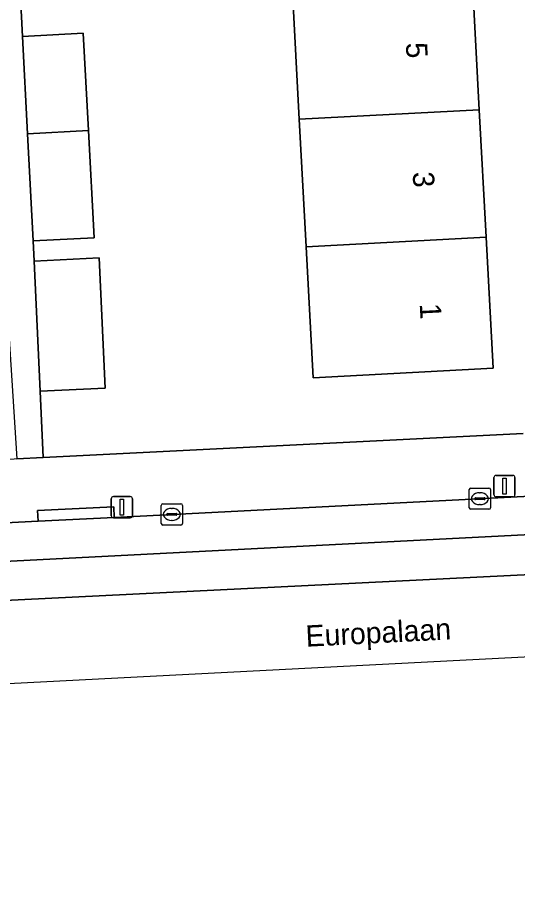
# Model space of a CAD drawing. Extents: x 160554 to 161248, y 385329 to 386506.
# Drawn here: x 161046.43 to 161069.93, y 385329.84 to 385370.85 of the extents above; entities that cross this region are included whole.
import ezdxf

# ---------------------------------------------------------------- set-up
doc = ezdxf.new("R2010")
doc.units = 0
for name, color, linetype in [('IMGEO_Erf', 7, 'Continuous'), ('IMGEO_Fietspad_gesloten', 7, 'Continuous'), ('IMGEO_Kolk', 7, 'Continuous'), ('IMGEO_Lichtmast', 7, 'Continuous'), ('IMGEO_Openbare_ruimte_label', 7, 'Continuous'), ('IMGEO_Pand', 7, 'Continuous'), ('IMGEO_Pand_nummerreeks', 7, 'Continuous'), ('IMGEO_Parkeervlak_open', 7, 'Continuous'), ('IMGEO_Rijbaan_lokaal_gesloten', 7, 'Continuous'), ('IMGEO_Voetpad_open', 7, 'Continuous')]:
    doc.layers.add(name, color=color, linetype=linetype)

msp = doc.modelspace()

# ---------------------------------------------------------------- linework, layer by layer
at = {"layer": 'IMGEO_Erf'}
msp.add_lwpolyline([(161071.268, 385380.026), (161071.234, 385380.712), (161049.014, 385379.232), (161049.037, 385378.813), (161049.294, 385374.124), (161046.467, 385373.975), (161046.673, 385369.959), (161049.514, 385370.11), (161049.765, 385365.531), (161050.041, 385360.489), (161047.165, 385360.352), (161047.214, 385359.396), (161050.272, 385359.538), (161050.557, 385353.425), (161047.498, 385353.283), (161047.643, 385350.154), (161070.196, 385351.283)], dxfattribs=at)
msp.add_lwpolyline([(161059.994, 385360.067), (161059.675, 385366.059), (161059.356, 385372.05), (161059.027, 385378.212), (161067.484, 385378.663), (161067.812, 385372.501), (161068.132, 385366.51), (161068.451, 385360.518), (161068.779, 385354.357), (161060.323, 385353.906)], close=True, dxfattribs=at)
at = {"layer": 'IMGEO_Fietspad_gesloten'}
msp.add_lwpolyline([(161073.593, 385346.692), (161010.368, 385343.456), (161010.036, 385343.439), (161000, 385342.925), (160998.286, 385342.836), (160996.326, 385342.732), (160947.774, 385340.274), (160938.967, 385339.846), (160935.209, 385339.663), (160934.649, 385339.636), (160923.236, 385339.08), (160923.045, 385339.071), (160906.536, 385338.204), (160879.509, 385336.797), (160869.015, 385336.349), (160868.229, 385336.325), (160868.279, 385334.438), (160939.068, 385337.926), (161034.402, 385342.87), (161141.871, 385348.183)], dxfattribs=at)
at = {"layer": 'IMGEO_Kolk'}
for p, q in [((161067.661, 385347.796), (161067.661, 385348.648)), ((161067.736, 385348.722), (161068.588, 385348.722)), ((161068.662, 385348.648), (161068.662, 385347.796)), ((161067.92, 385348.216), (161067.92, 385348.228)), ((161068.358, 385348.179), (161067.96, 385348.179)), ((161067.963, 385348.265), (161068.361, 385348.265)), ((161068.149, 385348.502), (161068.174, 385348.502)), ((161068.404, 385348.228), (161068.404, 385348.216)), ((161053.186, 385347.057), (161053.186, 385347.909)), ((161053.261, 385347.983), (161054.113, 385347.983)), ((161053.674, 385347.763), (161053.699, 385347.763)), ((161054.187, 385347.909), (161054.187, 385347.057)), ((161068.588, 385347.722), (161067.736, 385347.722)), ((161068.172, 385347.942), (161068.147, 385347.942)), ((161053.445, 385347.477), (161053.445, 385347.489)), ((161053.883, 385347.44), (161053.485, 385347.44)), ((161053.488, 385347.526), (161053.886, 385347.526)), ((161053.929, 385347.489), (161053.929, 385347.477)), ((161054.113, 385346.983), (161053.261, 385346.983)), ((161053.697, 385347.203), (161053.672, 385347.203))]:
    msp.add_line(p, q, dxfattribs=at)
for points in [[(161067.661, 385347.796), (161067.661, 385348.648)], [(161067.736, 385348.722), (161068.588, 385348.722)], [(161068.662, 385348.648), (161068.662, 385347.796)], [(161053.186, 385347.057), (161053.186, 385347.909)], [(161053.261, 385347.983), (161054.113, 385347.983)], [(161054.187, 385347.909), (161054.187, 385347.057)], [(161068.588, 385347.722), (161067.736, 385347.722)], [(161054.113, 385346.983), (161053.261, 385346.983)]]:
    msp.add_lwpolyline(points, dxfattribs=at)
for centre, radius, start, end in [((161067.738, 385348.646), 0.0765, 91.552, 178.448), ((161067.738, 385348.646), 0.0765, 91.552, 178.448), ((161068.586, 385348.646), 0.0765, 1.552, 88.448), ((161068.586, 385348.646), 0.0765, 1.552, 88.448), ((161067.96, 385348.225), 0.0403, 85.8775, 175.7526), ((161067.957, 385348.215), 0.0366, 178.938, 274.7102), ((161068.361, 385348.222), 0.043, 264.8664, 352.4533), ((161068.365, 385348.227), 0.0386, 1.7309, 96.639), ((161053.263, 385347.907), 0.0765, 91.552, 178.448), ((161053.263, 385347.907), 0.0765, 91.552, 178.448), ((161054.111, 385347.907), 0.0765, 1.552, 88.448), ((161054.111, 385347.907), 0.0765, 1.552, 88.448), ((161067.738, 385347.798), 0.0765, 181.552, 268.448), ((161067.738, 385347.798), 0.0765, 181.552, 268.448), ((161068.586, 385347.798), 0.0765, 271.552, 358.448), ((161068.586, 385347.798), 0.0765, 271.552, 358.448), ((161053.485, 385347.486), 0.0403, 85.8775, 175.7526), ((161053.482, 385347.476), 0.0366, 178.938, 274.7102), ((161053.886, 385347.483), 0.043, 264.8664, 352.4533), ((161053.89, 385347.488), 0.0386, 1.7309, 96.639), ((161053.263, 385347.059), 0.0765, 181.552, 268.448), ((161053.263, 385347.059), 0.0765, 181.552, 268.448), ((161054.111, 385347.059), 0.0765, 271.552, 358.448), ((161054.111, 385347.059), 0.0765, 271.552, 358.448)]:
    msp.add_arc(centre, radius, start, end, dxfattribs=at)
for centre, major_axis, ratio, start_param, end_param in [((161068.148, 385348.222), (-0.387, 0.002), 0.722429, 4.712389, 7.853982), ((161068.173, 385348.222), (-0.39, 0.002), 0.717154, 1.570796, 4.712389), ((161053.673, 385347.483), (-0.387, 0.002), 0.722429, 4.712389, 7.853982), ((161053.698, 385347.483), (-0.39, 0.002), 0.717154, 1.570796, 4.712389)]:
    msp.add_ellipse(centre, major_axis=major_axis, ratio=ratio, start_param=start_param, end_param=end_param, dxfattribs=at)
at = {"layer": 'IMGEO_Lichtmast'}
for p, q in [((161068.822, 385348.416), (161068.822, 385349.216)), ((161068.822, 385349.216), (161068.822, 385348.416)), ((161068.922, 385349.316), (161069.712, 385349.316)), ((161069.712, 385349.316), (161068.922, 385349.316)), ((161069.812, 385349.216), (161069.812, 385348.416)), ((161069.812, 385348.416), (161069.812, 385349.216)), ((161050.84, 385347.422), (161050.84, 385348.222)), ((161050.84, 385348.222), (161050.84, 385347.422)), ((161050.94, 385348.322), (161051.73, 385348.322)), ((161051.73, 385348.322), (161050.94, 385348.322)), ((161051.83, 385348.222), (161051.83, 385347.422)), ((161051.83, 385347.422), (161051.83, 385348.222)), ((161069.712, 385348.316), (161068.922, 385348.316)), ((161068.922, 385348.316), (161069.712, 385348.316)), ((161051.73, 385347.322), (161050.94, 385347.322)), ((161050.94, 385347.322), (161051.73, 385347.322))]:
    msp.add_line(p, q, dxfattribs=at)
for points in [[(161069.242, 385349.191), (161069.392, 385349.191), (161069.392, 385348.441), (161069.242, 385348.441), (161069.242, 385349.191)], [(161051.26, 385348.197), (161051.41, 385348.197), (161051.41, 385347.447), (161051.26, 385347.447), (161051.26, 385348.197)]]:
    msp.add_lwpolyline(points, dxfattribs=at)
for centre, start, end in [((161068.922, 385349.216), 90, 180), ((161068.922, 385349.216), 90, 180), ((161069.712, 385349.216), 0, 90), ((161069.712, 385349.216), 360, 90), ((161050.94, 385348.222), 90, 180), ((161050.94, 385348.222), 90, 180), ((161051.73, 385348.222), 0, 90), ((161051.73, 385348.222), 360, 90), ((161068.922, 385348.416), 180, 270), ((161068.922, 385348.416), 180, 270), ((161069.712, 385348.416), 270, 0), ((161069.712, 385348.416), 270, 0), ((161050.94, 385347.422), 180, 270), ((161050.94, 385347.422), 180, 270), ((161051.73, 385347.422), 270, 0), ((161051.73, 385347.422), 270, 0)]:
    msp.add_arc(centre, 0.1, start, end, dxfattribs=at)
at = {"layer": 'IMGEO_Pand'}
for points in [[(161068.132, 385366.51), (161067.812, 385372.501), (161059.356, 385372.05), (161059.675, 385366.059)], [(161049.765, 385365.531), (161049.514, 385370.11), (161046.673, 385369.959), (161046.908, 385365.379)], [(161068.451, 385360.518), (161068.132, 385366.51), (161059.675, 385366.059), (161059.994, 385360.067)], [(161046.908, 385365.379), (161047.165, 385360.352), (161050.041, 385360.489), (161049.765, 385365.531)], [(161059.994, 385360.067), (161060.323, 385353.906), (161068.779, 385354.357), (161068.451, 385360.518)], [(161047.498, 385353.283), (161050.557, 385353.425), (161050.272, 385359.538), (161047.214, 385359.396)]]:
    msp.add_lwpolyline(points, close=True, dxfattribs=at)
at = {"layer": 'IMGEO_Parkeervlak_open'}
for points in [[(161072.067, 385348.42), (161050.979, 385347.344), (161047.397, 385347.161), (161011.529, 385345.331)], [(161010.368, 385343.456), (161073.593, 385346.692)]]:
    msp.add_lwpolyline(points, dxfattribs=at)
at = {"layer": 'IMGEO_Rijbaan_lokaal_gesloten'}
for points in [[(160858.736, 385329.845), (160946.542, 385334.387), (161159.084, 385345.381), (161164.38, 385345.655), (161210, 385350.626), (161209.307, 385356.836), (161206.201, 385354.636)], [(161179.212, 385352.808), (161177.568, 385352.385), (161171.027, 385350.994), (161157.592, 385349.093), (161141.871, 385348.183), (161034.402, 385342.87), (160939.068, 385337.926), (160868.279, 385334.438), (160858.352, 385334.048), (160858.736, 385329.845)]]:
    msp.add_lwpolyline(points, dxfattribs=at)
at = {"layer": 'IMGEO_Voetpad_open'}
for points in [[(161071.234, 385380.712), (161071.191, 385381.596), (161053.913, 385380.638), (161049.079, 385380.37), (161044.387, 385380.11), (161041.955, 385379.921), (161041.988, 385379.402), (161042.047, 385378.446), (161044.568, 385378.607), (161046.395, 385350.091), (161047.643, 385350.154), (161047.498, 385353.283), (161047.214, 385359.396), (161047.165, 385360.352), (161046.908, 385365.379), (161046.673, 385369.959), (161046.467, 385373.975), (161046.207, 385379.045), (161049.014, 385379.232)], [(161047.397, 385347.161), (161050.979, 385347.344), (161050.957, 385347.843), (161047.375, 385347.66)]]:
    msp.add_lwpolyline(points, close=True, dxfattribs=at)
for points in [[(161070.196, 385351.283), (161047.643, 385350.154), (161046.395, 385350.091), (161046.278, 385350.085), (161013.343, 385348.435), (161013.338, 385348.434), (161007.555, 385348.077), (161000.552, 385347.79), (160994.482, 385347.409), (160994.435, 385347.411), (160976.551, 385346.52), (160972.502, 385346.318), (160971.187, 385346.253), (160938.716, 385344.635), (160938.869, 385341.632), (160972.126, 385343.325), (160972.102, 385343.824), (160975.837, 385344.015), (160975.861, 385343.516), (160997.155, 385344.6)], [(161011.529, 385345.331), (161047.397, 385347.161), (161047.375, 385347.66), (161050.957, 385347.843), (161050.979, 385347.344), (161072.067, 385348.42)]]:
    msp.add_lwpolyline(points, dxfattribs=at)

# ---------------------------------------------------------------- texts
at = {"layer": 'IMGEO_Openbare_ruimte_label'}
msp.add_text('Europalaan', height=1, rotation=2.9225, dxfattribs=at).set_placement((161059.999, 385341.26))
at = {"layer": 'IMGEO_Pand_nummerreeks'}
for s, p in [('5', (161064.68, 385369.648)), ('3', (161065.003, 385363.571)), ('1', (161065.333, 385357.382))]:
    msp.add_text(s, height=1, rotation=273.0498, dxfattribs=at).set_placement(p)

doc.saveas('drawing.dxf')
